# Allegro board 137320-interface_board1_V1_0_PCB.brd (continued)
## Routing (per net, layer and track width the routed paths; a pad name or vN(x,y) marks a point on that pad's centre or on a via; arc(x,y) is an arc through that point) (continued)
N2499294: length 4.2
  TOP w0.152: v1(107.63,37.47) Q6.1 107.63,35.66 Q5.3
  BOTTOM w0.152: R189.1 108.08,37.02 v1(107.63,37.47)
N2500054: length 2.8
  TOP w0.152: R193.1 103.18,41.22 U51.13
N2500096: length 3.5
  TOP w0.152: R194.1 105.78,31.65 U51.8
N2500172: length 4.2
  TOP w0.152: v1(110.8,53.34) Q8.1 110.8,51.54 Q7.3
  BOTTOM w0.152: v1(110.8,53.34) 111.25,52.89 R195.1
N2500268: length 4.2
  TOP w0.152: Q9.3 107.63,51.54 Q10.1 v1(107.63,53.34)
  BOTTOM w0.152: R197.1 108.08,52.89 v1(107.63,53.34)
N2500326: length 11.3
  TOP w0.152: Q8.3 Q10.3 107.48,54.39 106.17,53.09 104.73,53.09 104.48,53.34 U52.11 104.48,55.46 v1(104.78,55.75)
  BOTTOM w0.152: v1(104.78,55.75) R196.1
N2500498: length 2.8
  TOP w0.152: U52.13 103.18,57.09 R200.1
N2500522: length 3.5
  TOP w0.152: R201.1 105.78,47.52 U52.8
N2500778: length 2.4
  TOP w0.152: C222.2 103.5,46.86 103.18,47.19 U52.4
N2500782: length 2.4
  TOP w0.152: U52.3 102.53,47.16 102.23,46.86 C224.1
N2500790: length 2.7
  TOP w0.152: U52.7 105.13,47.65 106.05,46.74 C220.1
N2500794: length 7.7
  TOP w0.152: U52.2 101.88,47.12 101.6,46.84 101.6,44.07 101.85,43.81 103,43.81 103.5,44.32 C222.1
N2500802: length 4.2
  TOP w0.152: U52.6 104.48,47.54 105.41,46.61 105.41,45.47 105.16,45.21 C223.2
N2500814: length 2.7
  TOP w0.152: U52.12 103.83,55.7 R203.2
N2500826: length 2.7
  TOP w0.152: U52.5 103.83,47.17 C223.1
N2500830: length 2.4
  TOP w0.152: R202.1 100.97,46.86 101.23,47.13 U52.1
N2500842: length 2.9
  TOP w0.152: U52.16 101.23,55.11 R204.2
N2500874: length 2.4
  TOP w0.152: U52.9 105.78,56.38 R205.2
N2500938: length 2.5
  TOP w0.152: R205.1 R207.2 R206.2
N21751111: length 3.6
  TOP w0.152: D15.1 82.55,53.47 82.55,52.96 R41.2
N21777191: length 3.1
  TOP w0.152: 29.21,40.51 28.57,41.15 28.57,42.42 U11.2
N21777192: length 2.5
  TOP w0.152: 30.48,40.51 U11.3
N23783590: length 3.1
  BOTTOM w0.152: R63.1 29.84,50.29 29.84,49.66 30.48,49.02 U12.3
N23783591: length 3.1
  BOTTOM w0.152: R64.2 28.57,50.29 28.57,49.66 29.21,49.02 U12.2
N23815910: length 2.4
  TOP w0.152: U7.3 v1(135.89,9.91)
  BOTTOM w0.152: R44.1 v1(135.89,9.91)
N23815911: length 2.4
  TOP w0.152: U7.2 v1(134.62,9.91)
  BOTTOM w0.152: R46.2 v1(134.62,9.91)
N23839151: length 3.1
  TOP w0.152: 39.37,40.51 38.73,41.15 38.73,42.42 U13.2
N23839152: length 2.5
  TOP w0.152: 40.64,40.51 U13.3
N23839610: length 3.1
  BOTTOM w0.152: R69.1 40.01,50.29 40.01,49.66 40.64,49.02 U14.3
N23840811: length 3.1
  BOTTOM w0.152: U14.2 39.37,49.02 38.73,49.66 38.73,50.29 R70.2
N23858251: length 3.1
  TOP w0.152: 49.53,40.51 48.9,41.15 48.9,42.42 U15.2
N23858252: length 2.5
  TOP w0.152: 50.8,40.51 U15.3
N23858410: length 3.1
  BOTTOM w0.152: U16.3 50.8,49.02 50.16,49.66 50.16,50.29 R75.1
N23859371: length 3.1
  BOTTOM w0.152: R76.2 48.9,50.29 48.9,49.66 49.53,49.02 U16.2
N23877351: length 3.1
  TOP w0.152: U17.2 28.57,26.54 28.57,25.27 R79.2
N23877352: length 2.5
  TOP w0.152: R77.1 U17.3
N23877510: length 3.1
  BOTTOM w0.152: R81.1 29.84,34.42 29.84,33.78 30.48,33.15 U18.3
N23878471: length 3.1
  BOTTOM w0.152: U18.2 29.21,33.15 28.57,33.78 28.57,34.42 R82.2
N23893201: length 3.1
  TOP w0.152: R84.2 38.73,25.27 38.73,26.54 U19.2
N23893202: length 2.5
  TOP w0.152: R83.1 U19.3
N23893360: length 3.1
  BOTTOM w0.152: R87.1 40.01,34.42 40.01,33.78 40.64,33.15 U20.3
N23894321: length 3.1
  BOTTOM w0.152: U20.2 39.37,33.15 38.73,33.78 38.73,34.42 R88.2
N23909051: length 3.1
  TOP w0.152: R90.2 48.9,25.27 48.9,26.54 U21.2
N23909052: length 2.5
  TOP w0.152: R89.1 U21.3
N23909210: length 3.1
  BOTTOM w0.152: R93.1 50.16,34.42 50.16,33.78 50.8,33.15 U22.3
N23910171: length 3.1
  BOTTOM w0.152: R94.2 48.9,34.42 48.9,33.78 49.53,33.15 U22.2
N23924901: length 3.1
  TOP w0.152: R98.2 28.57,9.4 28.57,10.67 U23.2
N23924902: length 2.5
  TOP w0.152: R95.1 U23.3
N23925060: length 3.1
  BOTTOM w0.152: R99.1 29.84,18.54 29.84,17.91 30.48,17.27 U24.3
N23926021: length 3.1
  BOTTOM w0.152: U24.2 29.21,17.27 28.57,17.91 28.57,18.54 R100.2
N23940751: length 3.1
  TOP w0.152: U25.2 38.73,10.67 38.73,9.4 R104.2
N23940752: length 2.5
  TOP w0.152: R101.1 U25.3
N23940910: length 3.1
  BOTTOM w0.152: U26.3 40.64,17.27 40.01,17.91 40.01,18.54 R105.1
N23941871: length 3.1
  BOTTOM w0.152: U26.2 39.37,17.27 38.73,17.91 38.73,18.54 R106.2
N23956601: length 3.1
  TOP w0.152: U27.2 48.9,10.67 48.9,9.4 R108.2
N23956602: length 2.5
  TOP w0.152: R107.1 U27.3
N23956760: length 3.1
  BOTTOM w0.152: R111.1 50.16,18.54 50.16,17.91 50.8,17.27 U28.3
N23957721: length 3.1
  BOTTOM w0.152: U28.2 49.53,17.27 48.9,17.91 48.9,18.54 R112.2
N24852551: length 3.1
  TOP w0.152: R169.2 110.49,9.4 110.49,10.03 109.86,10.67 109.86,11.3
N24852552: length 2.5
  TOP w0.152: R167.1 U47.3
N24852710: length 2.5
  BOTTOM w0.152: U48.3 R166.1
N24853671: length 3.1
  BOTTOM w0.152: R168.2 110.49,18.54 110.49,17.91 109.86,17.27 109.86,16.64
N24867031: length 3.1
  TOP w0.152: U49.2 120.65,10.67 121.28,10.03 121.28,9.4 R174.2
N24867032: length 2.5
  TOP w0.152: R172.1 U49.3
N24867190: length 2.5
  BOTTOM w0.152: U50.3 R171.1
N24868151: length 3.1
  BOTTOM w0.152: U50.2 120.65,17.27 121.28,17.91 121.28,18.54 R173.2

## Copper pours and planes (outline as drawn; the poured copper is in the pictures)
GND on TOP (solid shape): 32.64,81.28 32.64,77.85 32.51,77.72 25.65,77.72 25.53,77.85 25.53,81.28 25.65,81.41 32.51,81.41
GND on TOP (solid shape): 32.64,67.18 32.64,63.75 32.51,63.63 25.65,63.63 25.53,63.75 25.53,67.18 25.65,67.31 32.51,67.31
GND on TOP (solid shape): 53.72,75.95 53.72,73.66 53.59,73.53 49.28,73.53 49.15,73.66 49.15,75.95 49.28,76.07 53.59,76.07
GND on TOP (solid shape): 63.75,77.72 64.01,77.72 64.01,78.36 64.26,78.36 64.26,77.72 64.52,77.72 64.52,78.36 64.77,78.36 64.77,77.72 65.02,77.72 65.02,78.36 65.28,78.36 65.28,74.55 67.18,72.64 67.18,70.36 67.06,70.23 63.75,70.23 63.63,70.36 63.63,72.39 63.25,72.77 63.88,72.77 63.88,73.03 63.5,73.03 63.5,72.77 63.25,72.77 63.12,72.9 63.12,73.28 63.25,73.41 64.14,73.41 64.52,73.79 64.52,74.68 65.02,74.68 65.02,75.44 64.77,75.44 64.77,74.68 64.52,74.68 64.52,75.56 64.39,75.69 63.63,75.69 63.5,75.82 63.5,78.36 63.75,78.36
GND on TOP (solid shape): 93.34,37.97 93.6,37.97 93.6,38.61 93.85,38.61 93.85,37.97 94.11,37.97 94.11,38.61 94.36,38.61 94.36,37.97 94.61,37.97 94.61,38.61 94.87,38.61 94.87,34.92 95.63,34.16 95.63,30.73 95.5,30.61 94.23,30.61 94.11,30.73 94.11,32.77 93.85,33.02 94.49,33.02 94.49,33.27 94.11,33.27 94.11,33.02 93.85,33.02 93.73,33.15 93.73,33.53 94.49,33.53 94.49,33.78 94.11,33.78 94.11,33.53 93.73,33.53 93.73,33.66 94.11,34.04 94.11,34.92 94.61,34.92 94.61,35.69 94.36,35.69 94.36,34.92 94.11,34.92 94.11,35.81 93.98,35.94 93.22,35.94 93.09,36.07 93.09,38.61 93.34,38.61
GND on BOTTOM (solid shape): 22.61,66.55 22.61,64.77 22.48,64.64 18.03,64.64 17.91,64.77 17.91,66.55 18.03,66.67 22.48,66.67
GND on BOTTOM (solid shape): 22.99,80.01 22.99,75.69 22.86,75.56 20.95,75.56 20.83,75.69 20.83,80.01 20.95,80.14 22.86,80.14
GND on BOTTOM (solid shape): 43.43,56.26 43.43,53.98 43.31,53.85 39.12,53.85 38.99,53.98 38.99,56.26 39.12,56.39 43.31,56.39
GND on BOTTOM (solid shape): 62.36,68.07 62.36,64.01 62.23,63.88 59.82,63.88 59.69,64.01 59.69,68.07 59.82,68.2 62.23,68.2
GND on BOTTOM (solid shape): 67.69,62.74 67.69,61.21 67.56,61.09 65.66,61.09 65.53,61.21 65.53,62.74 65.66,62.87 67.56,62.87
GND on BOTTOM (solid shape): 69.34,50.55 69.34,48.26 69.22,48.13 65.79,48.13 65.66,48.26 65.66,50.55 65.79,50.67 69.22,50.67
GND on BOTTOM (solid shape): 69.98,77.34 69.98,75.82 69.85,75.69 63.63,75.69 63.5,75.82 63.5,77.34 63.63,77.47 69.85,77.47
GND on BOTTOM (solid shape): 99.57,37.59 99.57,36.07 99.44,35.94 93.22,35.94 93.09,36.07 93.09,37.59 93.22,37.72 99.44,37.72
GND on BOTTOM (solid shape): 106.43,13.84 106.43,10.41 106.3,10.29 103.25,10.29 103.12,10.41 103.12,13.84 103.25,13.97 106.3,13.97
GND on BOTTOM (solid shape): 46.23,70.74 46.23,66.93 46.1,66.8 43.81,66.8 43.69,66.93 43.69,70.74 43.81,70.87 46.1,70.87
GND on BOTTOM (solid shape): 32.64,83.44 32.64,78.99 32.51,78.87 25.65,78.87 25.53,78.99 25.53,83.44 25.65,83.57 32.51,83.57
GND on BOTTOM (solid shape): 36.32,65.66 45.47,65.66 45.59,65.53 45.59,64.01 45.47,63.88 33.78,63.88 32.77,64.9 25.65,64.9 25.53,65.02 25.53,69.34 25.65,69.47 32.51,69.47
GND on BOTTOM (solid shape): 101.73,69.47 101.73,64.52 101.6,64.39 97.41,64.39 97.28,64.52 97.28,66.29 97.41,66.42 98.3,66.42 99.19,67.31 99.19,69.47 99.31,69.6 101.6,69.6
GND on BOTTOM: 116.84,69.6 114.55,69.6 114.43,69.47 114.43,67.31 113.54,66.42 112.65,66.42 112.52,66.29 112.52,64.52 112.65,64.39 116.84,64.39 116.97,64.52 116.97,69.47
GND on BOTTOM: 91.57,66.8 90.04,66.8 89.92,66.93 89.92,74.04 90.04,74.17 91.57,74.17 91.69,74.04 91.69,66.93
GND on BOTTOM: 106.81,66.93 105.28,66.93 105.16,67.06 105.16,74.17 105.28,74.3 106.81,74.3 106.93,74.17 106.93,67.06
GND on GND02: 0.51,0.51 0.51,89.49 159.49,89.49 159.49,0.51 ; 1 cut-out
GND on POWER05: 0.51,0.51 0.51,89.49 21.97,89.49 21.97,0.51
GND on POWER05: 64.64,0.51 64.64,17.89 62.1,20.43 62.1,43.07 64.64,45.61 64.64,89.49 159.49,89.49 159.49,0.51 ; 1 cut-out
GND_ISO12 on GND02, POWER05: 130.19,22.54 129.67,23.07 129.67,34.08 130.19,34.61 137.9,34.61 138.43,34.08 138.43,23.07 137.9,22.54
GND_ISO13 on GND02, POWER05: 130.19,66.36 129.67,66.88 129.67,77.9 130.19,78.42 137.9,78.42 138.43,77.9 138.43,66.88 137.9,66.36
GND_ISO14 on GND02, POWER05: 130.19,37.15 129.67,37.67 129.67,48.69 130.19,49.21 137.9,49.21 138.43,48.69 138.43,37.67 137.9,37.15
GND_ISO15 on GND02, POWER05: 130.19,51.75 129.67,52.28 129.67,63.29 130.19,63.82 137.9,63.82 138.43,63.29 138.43,52.28 137.9,51.75
VCC_MAIN on TOP (solid shape): 53.72,81.28 53.72,77.72 53.59,77.6 49.28,77.6 49.15,77.72 49.15,81.28 49.28,81.41 53.59,81.41
VCC_MAIN on TOP (solid shape): 58.67,73.66 58.67,70.74 58.55,70.61 56.9,70.61 56.77,70.74 56.77,73.66 56.9,73.79 58.55,73.79
VCC_MAIN on BOTTOM (solid shape): 54.1,81.28 54.1,75.18 53.98,75.06 52.2,75.06 52.07,75.18 52.07,78.61 51.94,78.74 49.28,78.74 49.15,78.87 49.15,81.28 49.28,81.41 53.98,81.41
VCC_MAIN on TOP: 88.27,31.11 88.14,30.99 86.36,30.99 86.23,31.11 86.23,34.04 86.36,34.16 88.14,34.16 88.27,34.04
VCC_MAIN on BOTTOM: 86.23,32.38 86.23,34.04 86.36,34.16 89.66,34.16 100.97,22.86 100.97,21.34 100.84,21.21 99.06,21.21 90.68,29.59 86.49,29.59 84.96,28.07 59.69,28.07 59.56,28.19 59.56,29.97 59.69,30.1 83.95,30.1
VCC_MAIN on ART03: 110.49,17.65 111.82,18.99 112.97,18.99 113.28,18.67 116.33,18.67 117.22,17.78 120.78,17.78 120.9,17.91 120.9,19.68 120.14,20.45 119.25,20.45 118.49,21.21 116.97,21.21 116.08,22.1 101.73,22.1 100.71,23.11 99.06,23.11 98.93,22.99 98.93,21.34 102.62,17.65
VCC_MAIN on POWER05: 22.48,0.51 22.48,89.49 64.14,89.49 64.14,45.83 61.59,43.29 61.59,20.21 64.14,17.67 64.14,0.51 ; 1 cut-out
VCC_SPARE on TOP (solid shape): 116.59,63.75 116.59,61.98 116.46,61.85 99.44,61.85 99.31,61.98 99.31,63.75 99.44,63.88 116.46,63.88
VCC_SPARE on TOP (solid shape): 50.67,65.53 50.67,58.8 53.09,56.39 73.91,56.39 74.04,56.26 74.04,54.48 73.91,54.36 52.07,54.36 48.64,57.78 48.64,65.53 48.77,65.66 50.55,65.66
VCC_SPARE on BOTTOM (solid shape): 51.18,65.53 51.18,58.04 51.05,57.91 47.75,57.91 47.62,58.04 47.62,61.47 47.12,61.98 47.12,65.53 47.24,65.66 51.05,65.66
VCC_SPARE on BOTTOM (solid shape): 101.35,63.88 101.35,61.98 101.22,61.85 98.68,61.85 91.19,54.36 72.01,54.36 71.88,54.48 71.88,56.26 72.01,56.39 90.3,56.39 96.9,62.99 96.9,63.88 97.03,64.01 101.22,64.01
VCC_SPARE on BOTTOM (solid shape): 116.59,63.88 116.59,61.98 116.46,61.85 112.27,61.85 112.14,61.98 112.14,63.88 112.27,64.01 116.46,64.01
VCC_SPARE on ART04: 71.88,54.48 71.88,56.26 72.01,56.39 73.79,56.39 73.91,56.26 73.91,41.4 71.25,38.73 71.25,30.73 73.53,28.45 73.53,26.04 73.03,25.53 72.39,25.53 69.6,28.32 69.6,35.31 68.07,36.83 68.07,38.99 67.18,39.88 67.18,40.13 67.94,40.89 67.94,41.53 68.33,41.91 69.85,41.91 70.87,42.93 70.87,53.47
VCC_SPARE on ART04: 99.31,71.25 99.31,86.36 99.57,86.61 102.36,86.61 102.62,86.36 102.62,71.5 99.19,68.07 99.19,64.39 99.69,63.88 101.22,63.88 101.35,63.75 101.35,61.98 101.22,61.85 97.28,61.85 96.77,62.36 96.77,68.71
VDD33_MAIN on TOP (solid shape): 30.61,86.23 30.61,85.22 31.11,84.71 61.09,84.71 64.26,81.53 70.74,81.53 72.64,79.63 72.64,70.74 72.52,70.61 67.69,70.61 67.56,70.74 67.56,74.3 67.69,74.42 69.72,74.42 69.85,74.3 69.85,72.77 69.98,72.64 70.74,72.64 70.87,72.77 70.87,78.36 69.72,79.5 63.25,79.5 60.07,82.68 29.97,82.68 27.3,85.34 27.3,86.36 27.56,86.61 30.23,86.61
VDD33_MAIN on BOTTOM (solid shape): 69.98,74.17 69.98,70.74 69.85,70.61 67.56,70.61 67.44,70.74 67.44,74.17 67.56,74.3 69.85,74.3
VDD33_MAIN on TOP: 70.87,33.91 72.64,33.91 72.77,34.04 72.77,35.81 72.64,35.94 70.87,35.94 70.74,35.81 70.74,34.04
VDD33_MAIN on ART03: 72.26,70.61 67.82,70.61 67.69,70.74 67.69,72.52 67.82,72.64 73.66,72.64 79.88,66.42 82.93,66.42 85.85,63.5 85.85,60.83 85.72,60.71 81.15,60.71 80.64,61.21 80.64,62.23
VDD33_MAIN_485 on TOP (solid shape): 99.44,34.54 99.44,30.99 99.31,30.86 97.28,30.86 97.16,30.99 97.16,34.54 97.28,34.67 99.31,34.67
VDD33_MAIN_485 on BOTTOM (solid shape): 99.57,34.42 99.57,29.08 102.87,25.78 115.95,25.78 116.08,25.65 116.08,23.88 115.95,23.75 101.85,23.75 97.03,28.57 97.03,34.42 97.16,34.54 99.44,34.54
VDD33_MAIN_485 on ART03: 121.67,75.82 122.56,74.93 122.56,25.65 121.41,24.51 117.73,24.51 117.09,23.88 114.17,23.88 114.05,24 114.05,26.29 116.59,28.83 118.36,28.83 118.49,28.96 118.49,38.99 118.24,39.24 117.98,39.24 117.73,39.5 117.73,40.51 117.98,40.77 118.24,40.77 118.49,41.02 118.49,53.72 118.36,53.85 117.73,53.85 117.47,54.1 117.47,55.12 117.73,55.37 118.36,55.37 118.49,55.5 118.49,75.56 118.75,75.82
VDD33_RS232 on TOP (solid shape): 100.97,52.32 100.97,50.55 100.84,50.42 97.92,50.42 97.79,50.55 97.79,52.32 97.92,52.45 100.84,52.45
VDD33_RS232 on ART04: 112.52,32.89 109.09,32.89 108.84,33.15 108.84,40.26 108.71,40.39 106.68,40.39 106.55,40.26 106.55,38.35 104.65,36.45 98.93,36.45 97.66,37.72 97.66,57.66 98.93,58.93 106.81,58.93 108.2,57.53 108.2,54.74 108.84,54.1 112.9,54.1 113.54,53.47 113.54,49.4 113.03,48.9 109.35,48.9 108.2,50.04 107.44,50.04 107.06,49.66 107.06,49.02 112.9,43.18 112.9,39.24 113.03,39.12 113.03,33.4
VDD33_SPARE on TOP (solid shape): 96.65,53.85 96.65,52.07 96.52,51.94 94.74,51.94 94.61,52.07 94.61,53.85 94.74,53.98 96.52,53.98
VDD33_SPARE on TOP: 70.74,30.86 70.74,32.64 70.87,32.77 72.64,32.77 72.77,32.64 72.77,30.86 72.64,30.73 70.87,30.73
VDD33_SPARE on BOTTOM: 105.28,75.69 108.84,75.69 109.35,76.2 112.78,76.2 112.9,76.33 112.9,79.12 112.78,79.25 105.28,79.25 105.16,79.12 105.16,75.82
VDD33_SPARE on ART04: 88.27,21.97 88.01,22.23 88.01,28.57 89.28,29.84 89.28,55.12 95.63,61.47 101.73,61.47 103,62.74 103,77.85 103.38,78.23 103.38,86.49 103.5,86.61 106.43,86.61 106.55,86.49 106.55,79.88 107.19,79.25 107.19,77.34 105.03,75.18 105.03,61.47 102.87,59.31 98.3,59.31 96.65,57.66 96.65,50.55 93.22,47.12 93.22,22.23 92.96,21.97
VDD33_SPARE_485 on TOP (solid shape): 119.13,81.79 119.13,79.88 119,79.76 94.36,79.76 91.82,77.22 90.04,77.22 89.92,77.34 89.92,78.99 92.84,81.92 119,81.92
VDD33_SPARE_485 on TOP: 96.77,10.92 101.22,10.92 101.35,10.79 101.35,9.02 101.22,8.89 61.98,8.89 58.29,12.57 47.75,12.57 47.62,12.45 47.62,11.3 47.5,11.18 46.48,11.18 46.35,11.3 46.35,14.48 46.48,14.61 59.18,14.61 62.23,11.56 68.33,11.56 69.09,12.32 95.38,12.32
VDD33_SPARE_485 on BOTTOM: 90.04,75.69 93.6,75.69 94.11,76.2 97.54,76.2 97.66,76.33 97.66,79.12 97.54,79.25 90.04,79.25 89.92,79.12 89.92,75.82
VDD33_SPARE_485 on ART03: 111.12,9.65 108.46,9.65 106.81,11.3 103.25,11.3 102.23,10.29 97.16,10.29 96.39,11.05 96.39,12.57 97.16,13.34 107.95,13.34 109.35,11.94 119.89,11.94 120.9,10.92 120.9,9.65 120.78,9.53 118.75,9.53 117.47,10.79 112.27,10.79
VDD33_SPARE_485 on ART03: 30.1,41.91 30.99,41.02 36.96,41.02 37.85,41.91 39.5,41.91 40.39,41.02 47.12,41.02 48.01,41.91 50.04,41.91 50.8,41.15 50.8,40.13 50.16,39.5 27.56,39.5 27.43,39.62 27.43,41.66 27.69,41.91
VDD33_SPARE_485 on ART03: 27.43,23.62 27.43,26.16 27.56,26.29 49.78,26.29 49.91,26.16 49.91,23.62 49.66,23.37 27.69,23.37
VDD33_SPARE_485 on ART03: 27.69,11.18 43.56,11.18 45.59,13.21 49.28,13.21 49.78,12.7 49.78,9.4 49.28,8.89 27.69,8.89 27.56,9.02 27.56,11.05
VDD33_SPARE_485 on ART04: 118.49,30.86 118.36,30.99 117.86,30.99 117.6,31.24 117.6,32.26 117.86,32.51 118.36,32.51 118.49,32.64 118.49,45.59 118.24,45.85 117.73,45.85 117.6,45.97 117.6,46.74 117.73,46.86 118.24,46.86 118.49,47.12 118.49,60.07 118.36,60.2 117.86,60.2 117.6,60.45 117.6,61.47 117.86,61.72 118.36,61.72 118.49,61.85 118.49,68.33 118.36,68.45 117.86,68.45 117.6,68.71 117.6,69.72 117.86,69.98 118.36,69.98 118.49,70.1 118.49,78.61 117.47,79.63 117.47,81.41 117.6,81.53 121.03,81.53 122.94,79.63 122.94,20.07 122.05,19.18 122.05,10.03 121.54,9.53 118.62,9.53 118.49,9.65
VDD33_SPARE_485 on ART04: 25.27,9.4 29.46,9.4 29.59,9.53 29.59,13.59 27.43,15.75 27.43,22.48 29.84,24.89 29.84,26.29 26.42,29.72 26.42,37.97 29.46,41.02 29.46,41.91 29.34,42.04 24.51,42.04 24.38,41.91 24.38,10.29
VDD33_SWITCH on TOP (solid shape): 75.95,21.84 75.95,20.19 75.82,20.07 74.42,20.07 74.3,20.19 74.3,21.84 74.42,21.97 75.82,21.97
VDD33_SWITCH on BOTTOM (solid shape): 66.29,64.77 66.29,63.63 66.17,63.5 65.28,63.5 65.02,63.25 65.02,57.78 64.14,56.9 64.14,45.97 64.01,45.85 61.98,45.85 61.85,45.97 61.85,61.47 63.47,61.47 63.48,61.4 63.49,61.32 63.51,61.25 63.54,61.19 63.57,61.12 63.61,61.06 63.66,61.01 63.71,60.96 63.77,60.91 63.84,60.88 63.9,60.85 63.97,60.83 64.04,60.81 64.12,60.81 64.19,60.81 64.26,60.82 64.33,60.84 64.4,60.86 64.47,60.89 64.53,60.93 64.58,60.98 64.63,61.03 64.68,61.09 64.72,61.15 64.75,61.22 64.77,61.29 64.79,61.36 64.8,61.43 64.8,61.5 64.79,61.58 64.77,61.65 64.75,61.72 64.72,61.78 64.68,61.85 64.63,61.9 64.58,61.95 64.53,62 64.47,62.04 64.4,62.07 64.33,62.1 64.26,62.12 64.19,62.13 64.12,62.13 64.04,62.12 63.97,62.11 63.9,62.09 63.84,62.06 63.77,62.02 63.71,61.98 63.66,61.93 63.61,61.87 63.57,61.81 63.54,61.75 63.51,61.68 63.49,61.61 63.48,61.54 63.47,61.47 61.85,61.47 61.85,62.1 64.77,65.02 66.04,65.02
VDD33_SWITCH on ART03: 61.98,32.13 61.98,47.88 62.1,48.01 73.28,48.01 75.06,49.78 84.33,49.78 84.84,49.28 84.84,30.73 84.45,30.35 80.64,30.35 79.25,31.75 74.8,31.75 73.41,30.35 63.75,30.35
VDD33_SWITCH on ART04: 68.71,76.71 77.98,76.71 78.23,76.45 78.23,74.68 78.11,74.55 69.6,74.55 65.02,69.98 65.02,45.97 64.9,45.85 62.23,45.85 62.1,45.97 62.1,70.1
VDD33_SWITCH on ART04: 69.98,19.94 75.56,19.94 76.07,20.45 76.07,21.08 68.96,28.19 68.96,34.16 68.71,34.42 66.42,34.42 66.04,34.04 66.04,23.88
VIN28V_MAIN on BOTTOM (solid shape): outline of 184 points within 9.14,66.55 18.54,78.11
VIN28V_SPARE on BOTTOM (solid shape): outline of 158 points within 9.14,56.9 20.32,62.48
VIN_MAIN on TOP (solid shape): 32.64,76.07 32.64,72.64 32.51,72.52 25.65,72.52 25.53,72.64 25.53,76.07 25.65,76.2 32.51,76.2
VIN_MAIN on BOTTOM (solid shape): 39.75,75.44 39.75,72.52 39.12,71.88 36.83,71.88 35.18,70.23 21.84,70.23 19.3,72.77 19.3,74.68 19.43,74.8 33.78,74.8 34.54,75.56 39.62,75.56
VIN_SPARE on TOP (solid shape): 32.64,61.98 32.64,58.55 32.51,58.42 25.65,58.42 25.53,58.55 25.53,61.98 25.65,62.1 32.51,62.1
VIN_SPARE on BOTTOM (solid shape): 38.1,61.21 38.1,56.39 37.97,56.26 21.34,56.26 21.08,56.52 21.08,60.58 21.21,60.71 33.02,60.71 33.66,61.34 37.97,61.34
CON_MAIN_VBUS on BOTTOM (solid shape): 56.26,69.34 56.26,68.33 55.88,67.94 55.88,64.9 55.75,64.77 53.34,64.77 53.21,64.9 53.21,69.22 53.47,69.47 56.13,69.47
CON_MAIN_VBUS on TOP: 56.26,67.69 56.39,67.82 56.39,69.6 56.26,69.72 54.36,69.72 54.23,69.6 54.23,67.82 54.36,67.69
CON_SPARE_VBUS on TOP (solid shape): 106.93,19.94 106.93,18.16 106.81,18.03 104.65,18.03 104.52,18.16 104.52,19.94 104.65,20.07 106.81,20.07
CON_SPARE_VBUS on BOTTOM (solid shape): 106.93,20.32 106.93,17.91 106.81,17.78 103.63,17.78 103.5,17.91 103.5,20.32 103.63,20.45 106.81,20.45
MAIN_USB_VBUS on TOP (solid shape): 56.26,66.8 56.26,63.5 56.13,63.37 54.36,63.37 54.23,63.5 54.23,66.8 54.36,66.93 56.13,66.93
SPARE_USB_VBUS on TOP: 99.95,17.65 98.17,17.65 98.04,17.78 98.04,20.32 98.17,20.45 103.63,20.45 103.76,20.32 103.76,18.8 103.63,18.67 102.11,18.67 101.98,18.8 101.98,19.81 101.85,19.94 100.2,19.94 100.08,19.81 100.08,17.78
N2171436 on BOTTOM (solid shape): 48.26,78.49 48.26,74.3 50.29,72.26 50.29,68.96 50.16,68.83 47.88,68.83 47.75,68.96 47.75,70.87 45.34,73.28 45.34,75.56 46.1,76.33 46.1,78.49 46.23,78.61 48.13,78.61
N2173931 on TOP (solid shape): 63.12,76.71 62.48,76.71 62.48,76.45 63.12,76.45 63.12,76.2 62.48,76.2 62.48,75.95 63.12,75.95 63.12,75.44 63.25,75.31 63.75,75.31 63.75,74.8 63.25,74.3 62.99,74.3 62.61,73.91 62.61,72.77 62.1,72.26 62.1,70.36 61.98,70.23 59.56,70.23 59.44,70.36 59.44,72.77 62.23,72.77 62.23,73.03 61.85,73.03 61.85,72.77 59.44,72.77 59.44,73.28 62.23,73.28 62.23,73.53 61.85,73.53 61.85,73.28 59.44,73.28 59.44,74.17 62.23,76.96 63.12,76.96
N2174033 on TOP (solid shape): 69.85,76.83 69.85,75.82 69.72,75.69 65.66,75.69 65.66,75.95 66.29,75.95 66.29,76.2 65.66,76.2 65.66,76.45 66.29,76.45 66.29,76.71 65.66,76.71 65.66,76.96 69.72,76.96
N2324503 on BOTTOM (solid shape): 112.9,73.53 112.9,67.82 112.78,67.69 109.6,67.69 109.47,67.82 109.47,68.07 110.36,68.96 110.36,69.47 109.35,70.48 109.35,73.53 109.47,73.66 112.78,73.66
N2325487 on BOTTOM (solid shape): 111,67.18 111,64.39 111.38,64.01 111.38,63.12 111.25,62.99 109.47,62.99 109.35,63.12 109.35,67.18 109.47,67.31 110.87,67.31
N2327690 on BOTTOM (solid shape): 45.09,61.34 45.09,58.04 44.96,57.91 38.73,57.91 38.61,58.04 38.61,61.21 38.73,61.34 38.99,61.34 39.75,60.58 40.51,60.58 41.4,61.47 44.96,61.47
N2333053 on BOTTOM (solid shape): 69.98,60.45 69.98,52.96 69.85,52.83 68.07,52.83 67.94,52.96 67.94,58.67 67.56,59.05 67.56,60.45 67.69,60.58 69.85,60.58
N2333454 on BOTTOM (solid shape): 67.06,66.67 67.06,66.04 67.31,65.79 67.31,63.5 67.06,63.5 67.06,64.9 66.8,64.9 66.8,63.5 66.55,63.5 66.55,65.53 66.29,65.79 66.29,66.67 66.42,66.8 66.93,66.8
N2358897 on TOP (solid shape): 73.53,20.95 73.53,19.68 73.66,19.56 73.66,18.8 73.53,18.67 70.87,18.67 70.36,19.18 70.36,19.3 72.03,19.3 72.04,19.24 72.05,19.18 72.07,19.12 72.1,19.07 72.13,19.01 72.17,18.97 72.22,18.93 72.27,18.89 72.32,18.86 72.38,18.84 72.44,18.83 72.5,18.82 72.56,18.82 72.62,18.83 72.68,18.85 72.74,18.88 72.79,18.91 72.84,18.95 72.89,18.99 72.92,19.04 72.95,19.09 72.98,19.15 72.99,19.21 73,19.27 73,19.34 72.99,19.4 72.98,19.46 72.95,19.51 72.92,19.57 72.89,19.62 72.84,19.66 72.79,19.7 72.74,19.73 72.68,19.76 72.62,19.78 72.56,19.79 72.5,19.79 72.44,19.78 72.38,19.77 72.32,19.75 72.27,19.72 72.22,19.68 72.17,19.64 72.13,19.59 72.1,19.54 72.07,19.49 72.05,19.43 72.04,19.37 72.03,19.3 70.36,19.3 70.36,19.43 72.01,21.08 73.41,21.08
N2361697 on TOP (solid shape): 92.71,36.96 92.08,36.96 92.08,36.7 92.71,36.7 92.71,36.45 92.08,36.45 92.08,36.2 92.71,36.2 92.71,35.69 92.84,35.56 93.34,35.56 93.34,35.05 92.84,34.54 92.84,34.04 93.22,33.66 93.22,33.15 92.84,32.77 92.84,30.61 92.71,30.48 89.15,30.48 89.03,30.61 89.03,33.02 92.84,33.02 92.84,33.27 92.46,33.27 92.46,33.02 89.03,33.02 89.03,33.53 92.84,33.53 92.84,33.78 92.46,33.78 92.46,33.53 89.03,33.53 89.03,34.42 91.82,37.21 92.71,37.21
N2361891 on TOP (solid shape): 99.44,37.08 99.44,36.07 99.31,35.94 95.25,35.94 95.25,36.2 95.89,36.2 95.89,36.45 95.25,36.45 95.25,36.7 95.89,36.7 95.89,36.96 95.25,36.96 95.25,37.21 99.31,37.21
N2363053 on BOTTOM (solid shape): 97.66,73.53 97.66,67.82 97.54,67.69 94.36,67.69 94.23,67.82 94.23,68.07 95.12,68.96 95.12,69.47 94.11,70.48 94.11,73.53 94.23,73.66 97.54,73.66
N2363241 on BOTTOM (solid shape): 95.76,67.18 95.76,64.39 96.14,64.01 96.14,63.12 96.01,62.99 94.23,62.99 94.11,63.12 94.11,67.18 94.23,67.31 95.63,67.31

Small or netless copper shapes (teardrops, artwork), in the pictures only: 1 on TOP

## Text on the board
Ref Des/Silkscreen Bottom: ID5 | ID4 | ID6
Ref Des/Silkscreen Top: ID2 | ID3 | ID1 | interface_board1_V1.0 | 1 | 2
COMPVAL_TYPE_BOTTOM: FIGURE | SIZE | 10.0 | 32.0 | 37.0 | 40.0 | 120.0 | 157.0 | 174.0 | 62.0 | DRILL CHART: TOP to BOTTOM | ALL UNITS ARE IN MILS | PLATED | NON-PLATED | QTY | 1085 | 160 | 106 | 2 | 4 | 6 | 8
User.17: If the angle of PCB board outline is circular,please use this kind of break out area | If not use it,please delete it before you gerber out | If the angle of PCB board outline is right angle,please use this kind of break out area | AS usual,please use the 0.8MM stamp Via
